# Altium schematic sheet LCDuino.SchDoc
size A4
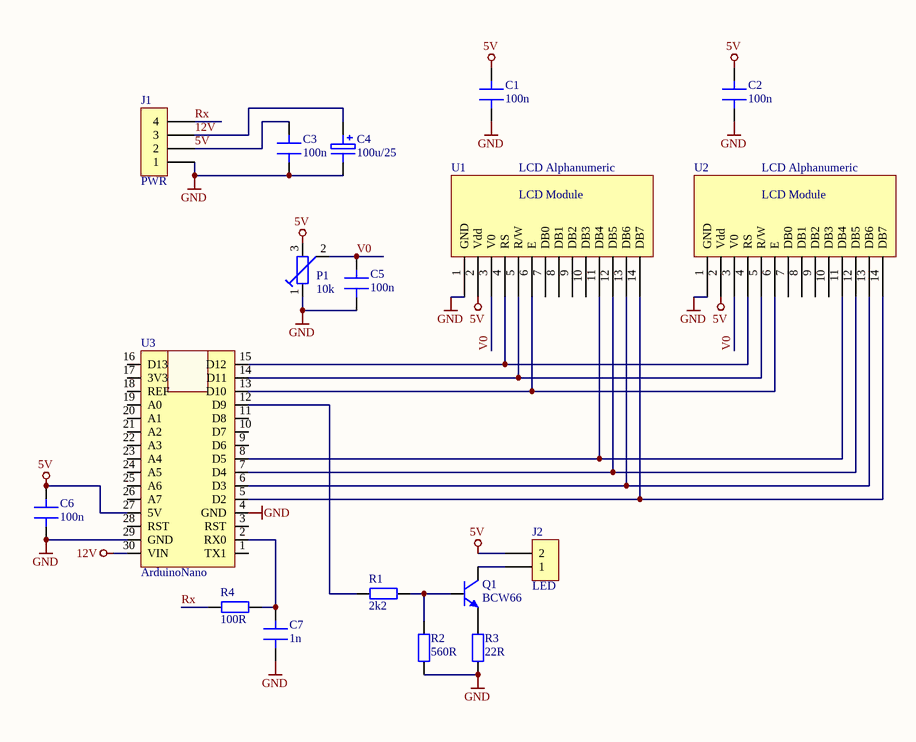
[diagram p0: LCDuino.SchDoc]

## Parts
C1  100n  [0805]
C2  100n  [0805]
C3  100n  [0805]
C4  100u/25  [SMD D]
C5  100n  [0805]
C6  100n  [0805]
C7  1n  [0805]
J1  PWR  [MTS04008]
J2  LED  [2pin100]
P1  10k  [CA6VSMD]
Q1  BCW66  [SOT23]
R1  2k2  [0805]
R2  560R  [0805]
R3  22R  [0805]
R4  100R  [0805]
U1  LCD Alphanumeric  [LCDM14pin]
U2  LCD Alphanumeric  [LCDM_2x7pin]
U3  ArduinoNano  [ArduinoNano]

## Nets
5V: C1.1 C2.1 C3.1 C6.1 J1.2 J2.2 P1.3 U1.2(Vdd) U2.2(Vdd) U3.27(5V)
12V: C4.1 J1.3 U3.30(VIN)
GND: C1.2 C2.2 C3.2 C4.2 C5.2 C6.2 C7.2 J1.1 P1.1 R2.1 R3.1 U1.1(GND) U2.1(GND) U3.4(GND) U3.29(GND)
Rx: J1.4 R4.1
V0: C5.1 P1.2 U1.3(V0) U2.3(V0)
NetC7_1: C7.1 R4.2 U3.2(RX0)
NetJ2_1: J2.1 Q1.3(C)
NetQ1_1: Q1.1(B) R1.2 R2.2
NetQ1_2: Q1.2(E) R3.2
NetR1_1: R1.1 U3.12(D9)
NetU1_4: U1.4(RS) U2.4(RS) U3.15(D12)
NetU1_5: U1.5(R/W) U2.5(R/W) U3.14(D11)
NetU1_6: U1.6(E) U2.6(E) U3.13(D10)
NetU1_11: U1.11(DB4) U2.11(DB4) U3.8(D5)
NetU1_12: U1.12(DB5) U2.12(DB5) U3.7(D4)
NetU1_13: U1.13(DB6) U2.13(DB6) U3.6(D3)
NetU1_14: U1.14(DB7) U2.14(DB7) U3.5(D2)

Not connected (* = marked no-connect by the designer): U1 7(DB0) 8(DB1) 9(DB2) 10(DB3); U2 7(DB0) 8(DB1) 9(DB2) 10(DB3); U3 1(TX1) 3(RST) 9(D6) 10(D7) 11(D8) 16(D13) 17(3V3) 18(REF) 19(A0) 20(A1) 21(A2) 22(A3) 23(A4) 24(A5) 25(A6) 26(A7) 28(RST)

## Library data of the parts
C1-C3 C5-C7 = C: kondenzator
C4 = C_EL: Kondenzator elektroliticky
J1 = CON4: Connector
J2 = CON2: Connector
P1 = TRIMER
Q1 = BCW66: NPN SMD
R1-R4 = R: Rezistor
U1 U2 = LCD_Modul: OLED
U3 = ArduinoNano: Arduino Nano V3.0 ATmega328 16M 5V CH340G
